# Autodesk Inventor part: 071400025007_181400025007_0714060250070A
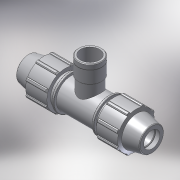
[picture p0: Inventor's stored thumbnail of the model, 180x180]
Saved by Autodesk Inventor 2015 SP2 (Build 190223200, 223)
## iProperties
Created: 2017-02
Part Number: 071400025007_181400025007_0714060250070A
Material: PVC-Piping
Description: PLASSON TEE WITH THREADED FEMALE OFFTAKE 25-3/4"-25
Document SubType Name: Modeling
Designer: KIM
Mass: 92.6774 g
Surface Area: 199.44 cm^2
Volume: 66.1981 cm^3
Density: 1.4 g/cm^3
Appearance: Smooth - White
Author: KIM
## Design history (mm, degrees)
derived "07140.ipt"
feature "Solid1::07140.ipt"
feature "Solid2::07140.ipt"
tag "TaggingFeature1"
body "Solid1"
other parameters: "d2" = 25, "d4" = 6.29167, "d5" = 18.12, "d7" = 54, "d11" = 2.51667, "d13" = 120 deg, "d14" = 37.5, "d15" = 12 deg, "d16" = 46.98, "d18" = 1.25, "d19" = 35 deg, "d20" = 17.5 deg, "d21" = 50.22, "d23" = 0, "d25" = 360 deg, "d27" = 1.08, "d33" = 0.5, "d42" = 27.18, "d43" = 1.62, "d46" = 0.75, "d68" = 4.53, "d72" = 48, "d76" = 24.117, "d80" = 0.72351, "d91" = 40.5, "d93" = 58, "d95" = 22.5, "d112" = 19, "d115" = 30.14625, "d116" = 135 deg, "d117" = 27.73455, "d118" = 151, "d119" = 22.5, "d121" = 0, "d122" = 22.5, "d124" = 0, "d128" = 0, "d129" = 2.5, "d130" = 5.7, "d131" = 0.3, "d132" = 0.3, "d133" = 30.14625, "d_" = 25, "E_" = 54, "A_" = 48, "l_" = 58, "l_2" = 19, "Rp_" = 24.117, "H_" = 151
